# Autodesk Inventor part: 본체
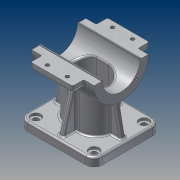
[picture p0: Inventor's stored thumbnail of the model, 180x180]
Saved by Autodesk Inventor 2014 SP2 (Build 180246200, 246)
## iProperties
Created: 2015-12
Part Number: 본체
Material: 알루미늄 6061
Document SubType Name: Modeling
Designer: mduedu
Density: 2.71 g/cm^3
Mass: 475.396 g
Surface Area: 479.255 cm^2
Volume: 175.423 cm^3
Appearance: 알루미늄 - 평지
Author: mduedu
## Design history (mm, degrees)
sketch "스케치1"
  geometry: L1 (45, 40)-(-45, 40); L2 (-45, 40)-(-45, -40); L3 (-45, -40)-(45, -40); L4 (45, -40)-(45, 40); L5 (45, 40)-(-45, -40); L6 (-45, 40)-(45, -40); 1 further point
  constraints: 12 end point, 2 midpoint, 2 parallel, 1 horizontal, 1 perpendicular
  dimensions: "d0" = 90 distance of L2.end L3.end; "d2" = 80 distance of L1.end L2.end
extrude "돌출1" new body sketch "스케치1" distance "d3" = 10; taper "d4" = 0 deg
sketch "스케치2"
  geometry: L1 (0, 40)-(0, -40) reference; C1 r 32.5 at (80, 0); 1 further point
  constraints: 1 centre point
  dimensions: "d5" = 65 diameter of C1; "d6" = 80 distance from line of C1.centre L1
extrude "돌출2" join sketch "스케치2" stored distance "d7" = 75; taper "d8" = 0 deg
sketch "스케치3"
  geometry: L1 (-27.5, -20)-(27.5, -20); L2 (27.5, -20)-(27.5, 20); L3 (27.5, 20)-(-27.5, 20); L4 (-27.5, 20)-(-27.5, -20); L5 (-27.5, -20)-(27.5, 20); L6 (27.5, -20)-(-27.5, 20); 1 further point
  constraints: 12 end point, 2 midpoint, 2 parallel, 1 horizontal, 1 perpendicular
  dimensions: "d9" = 55 distance of L2.end L3.end; "d11" = 40 distance of L1.end L2.end
extrude "돌출3" new body sketch "스케치3" stored distance "d12" = 75; taper "d13" = 0 deg
fillet "모깎기1"
fillet "모깎기2"
feature "결합1"
  node "솔리드2"
fillet "모깎기3" dims "d14" = 10
sketch "스케치4"
  geometry: L1 (-37.5, 47.5)-(37.5, 47.5) reference; L2 (35, 10)-(45, 10) reference; L3 (32.5, 47.5)-(40, 10); L4 (37.5, 47.5)-(37.5, 112.5) reference; L5 (45, 10)-(45, 0) reference; 1 further point
  constraints: 2 end point, 1 midpoint, 1 point on line
  dimensions: "d15" = 5 distance from line of L3.start L4; "d16" = 5 distance from line of L3.end L5
sketch "스케치5"
  geometry: L1 (10, 40)-(10, 30) reference; L2 (10, 35)-(56.569, 22.522); L3 (0, 40)-(10, 40) reference; 2 further points
  constraints: 2 end point, 1 midpoint, 2 other
  dimensions: "d17" = 5 distance from line of L2.start L3; "d18" = 15 deg angle of L2 L3
feature "리브1" dims "d19" = 1, "d20" = 6, "d21" = 0, "d22" = 0, "d23" = 1, "d24" = 1
feature "리브2" dims "d25" = 1, "d26" = 6, "d27" = 0, "d28" = 0, "d29" = 1, "d30" = 1
fillet "모깎기4" dims "d31" = 2
fillet "모깎기5" dims "d32" = 2
fillet "모깎기6" dims "d33" = 2
sketch "스케치6"
  geometry: A1 r 10 centre (-35, 30) between (-35, 40) and (-45, 30) reference; A2 r 10 centre (35, 30) between (45, 30) and (35, 40) reference; A3 r 10 centre (35, -30) between (35, -40) and (45, -30) reference; A4 r 10 centre (-35, -30) between (-45, -30) and (-35, -40) reference; 5 further points
  constraints: 4 coincident
hole "구멍1" sketch "스케치6" at (-35, 30), (35, 30), (35, -30), (-35, -30) diameter "d34" = 7; stored, may be unused: countersink angle "d38" = 90 deg, drill point angle "d40" = 118 deg; dims "d35" = 6, "d36" = 12, "d37" = 3, "d39" = 8
fillet "모깎기7" dims "d41" = 2
hole "구멍2" diameter "d44" = 45; stored, may be unused: countersink angle "d48" = 90 deg, drill point angle "d50" = 118 deg; dims "d42" = 10, "d43" = 10, "d45" = 6, "d46" = 4, "d47" = 2, "d49" = 8
sketch "스케치7" dims "d52" = 26.5
  geometry: L1 (0, 0)-(32.5, 0); L2 (0, 0)-(22.981, 22.981); A1 r 32.5 centre (0, 0) between (32.5, 0) and (22.981, 22.981) reference; 3 further points
  constraints: 4 end point, 2 point on circle, 1 coincident, 1 horizontal, 1 point on line, 3 other
  dimensions: "d51" = 45 deg angle of L2 L1
hole "구멍3" sketch "스케치7" at (18.738, 18.738) diameter "d54" = 2.459; stored, may be unused: countersink angle "d58" = 90 deg, drill point angle "d60" = 118 deg; dims "d55" = 8, "d56" = 4, "d57" = 2, "d59" = 10
sketch "스케치8"
  geometry: L1 (72.5, 31.623)-(72.5, 46); L2 (72.5, 46)-(87.5, 46); L3 (87.5, 46)-(87.5, 31.623); A1 r 32.5 centre (80, 0) between (87.5, 31.623) and (72.5, 31.623) reference; 2 further points
  constraints: 6 end point, 2 point on circle, 1 midpoint, 1 parallel, 1 vertical, 1 vertical alignment
  dimensions: "d64" = 15 distance of L1.end L2.end; "d66" = 46 distance from line of L2 A1.centre
extrude "돌출4" join sketch "스케치8" stored distance "d67" = 50; taper "d68" = 0 deg
fillet "모깎기8" dims "d69" = 3
fillet "모깎기9" dims "d70" = 2
sketch "스케치9"
  geometry: L1 (-76, 82.5)-(76, 82.5); L2 (76, 82.5)-(76, 0); L3 (76, 0)-(-76, 0); L4 (-76, 0)-(-76, 82.5); L5 (-46, 4.5)-(-46, -4.5) reference; C1 r 32.5 at (0, 0) reference; 2 further points
  constraints: 8 end point, 2 parallel, 1 coincident, 1 horizontal, 1 midpoint, 1 perpendicular
  dimensions: "d71" = 50 distance edge to line of C1 L1; "d72" = 30 distance between parallel lines of L4 L5
extrude "돌출5" cut sketch "스케치9" stored distance "d73" = 0; taper "d74" = 0 deg
node "작업 평면1"
sketch "스케치10"
  geometry: L1 (-7.5, 15)-(7.5, 15); L2 (-7.5, -15)-(7.5, -15); A1 r 20 centre (-7.5, 0) between (-7.5, 20) and (-26.977, 4.545) reference; A2 r 20 centre (7.5, 0) between (26.977, 4.545) and (7.5, 20) reference; A3 r 15 centre (-7.5, 0) between (-7.5, 15) and (-7.5, -15); A4 r 15 centre (7.5, 0) between (7.5, -15) and (7.5, 15); 1 further point
  constraints: 7 point on circle, 4 end point, 4 tangent, 3 point on line, 2 centre point, 2 coincident, 1 horizontal
  dimensions: "d77" = 5 radial gap between concentric circles of A3 A1
extrude "돌출6" cut sketch "스케치10" stored distance "d78" = 50; taper "d79" = 0 deg
fillet "모깎기10" dims "d80" = 3
sketch "스케치11"
  geometry: 2 further points
  constraints: 1 coincident
hole "구멍4" sketch "스케치11" at (0, 0) diameter "d81" = 12; stored, may be unused: countersink angle "d85" = 90 deg, drill point angle "d87" = 118 deg; dims "d82" = 8, "d83" = 40, "d84" = 10, "d86" = 10
sketch "스케치12"
  geometry: C1 r 10 at (0, 0); 1 further point
  constraints: 1 centre point, 1 coincident
  dimensions: "d88" = 20 diameter of C1
extrude "돌출7" cut sketch "스케치12" distance "d89" = 5; taper "d90" = 0 deg
chamfer "모따기1" distance "d91" = 1; stored, may be unused: second distance "d92" = 2, angle "d93" = 45 deg
fillet "모깎기11" dims "d94" = 0.5
feature "립1" dims "d95" = 1, "d96" = 1, "d97" = 0, "d98" = 3 deg, "d99" = 3 deg, "d100" = 0
sketch "스케치13"
  geometry: 4 further points
hole "구멍5" sketch "스케치13" at (34, 5.936), (10, -72.269), (34, -72.269), (10, 5.936) diameter "d101" = 4.5; stored, may be unused: countersink angle "d105" = 90 deg, drill point angle "d107" = 0 deg; dims "d102" = 6, "d103" = 4, "d104" = 2, "d106" = 8
fillet "모깎기12" dims "d115" = 0.3
node "솔리드1"
mirror "대칭1"
mirror "대칭2"
pattern_circular "원형 패턴1" dims angle "d62" = 360 deg
mirror "대칭3"
mirror "대칭4"
